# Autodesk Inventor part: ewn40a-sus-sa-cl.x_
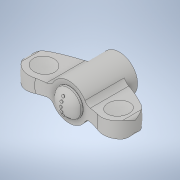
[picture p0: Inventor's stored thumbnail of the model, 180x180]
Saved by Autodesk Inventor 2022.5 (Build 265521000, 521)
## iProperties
Created: 2021-08
Part Number: ewn40a-sus-sa-cl.x_
Material: 一般
Document SubType Name: Modeling
Designer: ImaoCorp
Density: 1 g/cm^3
Appearance: 既定
Sending System: SOLIDWORKS 2019-2019304
MC: AMD64
MC_MODEL: Intel64 Family 6 Model 60 Stepping 3, GenuineIntel
OS: Windows_NT
FRU: Parasolid Version 31.0, build 290,  9- 1-2019
FORMAT: text
GUISE: transmit
KEY: ewn40a-sus-sa-cl
FILE: ewn40a-sus-sa-cl.x_t
DATE: Wed Aug 11 15:03:28 2021
Author: ImaoCorp
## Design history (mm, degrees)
feature "Base1"
node "ソリッド1"
